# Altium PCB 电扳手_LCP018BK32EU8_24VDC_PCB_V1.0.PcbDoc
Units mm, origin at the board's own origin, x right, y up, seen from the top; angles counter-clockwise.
Board outline 49.67 x 60.1 mm, 2 copper layers (Top Layer, Bottom Layer), stack 1.6 mm thick; 89 components, 55 nets, 390 pads, 196 vias.
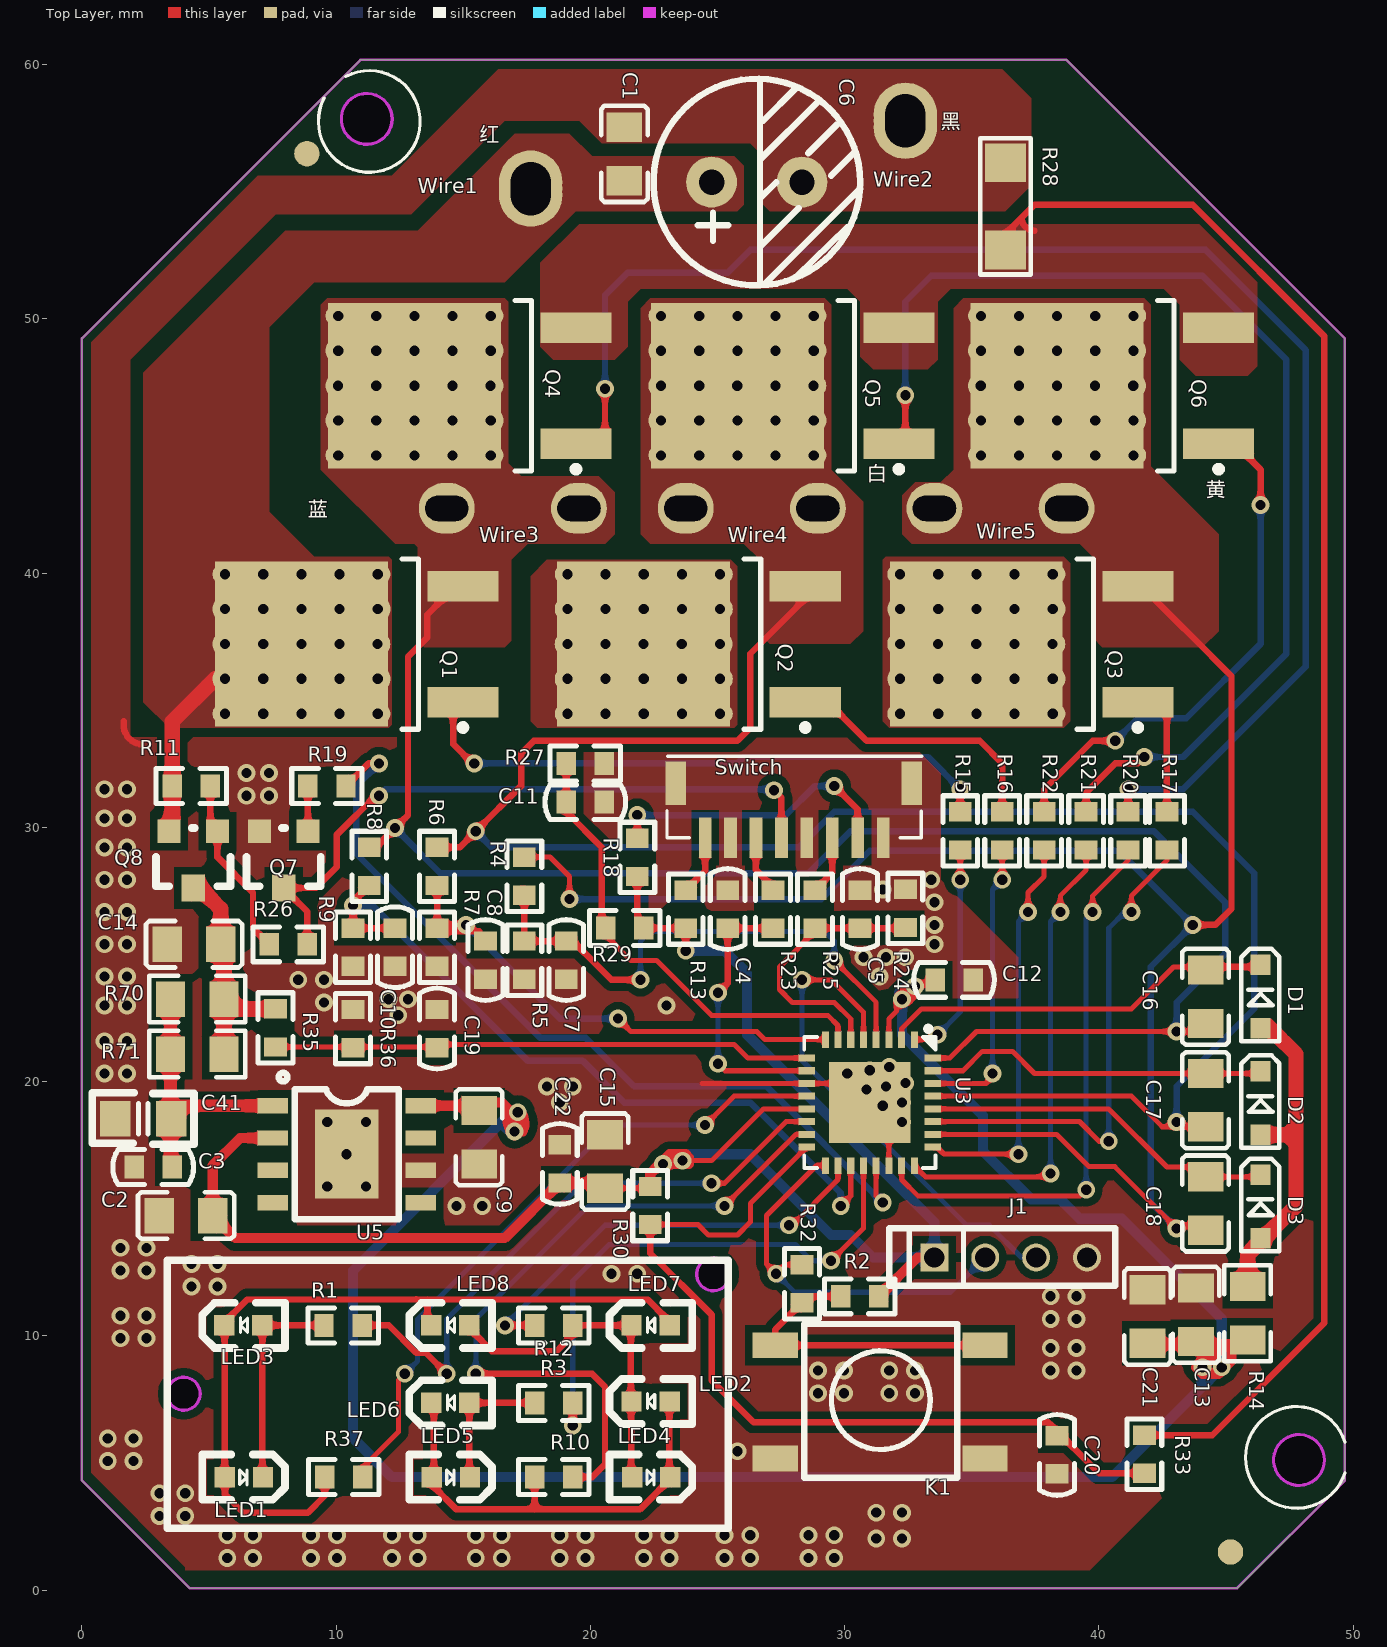
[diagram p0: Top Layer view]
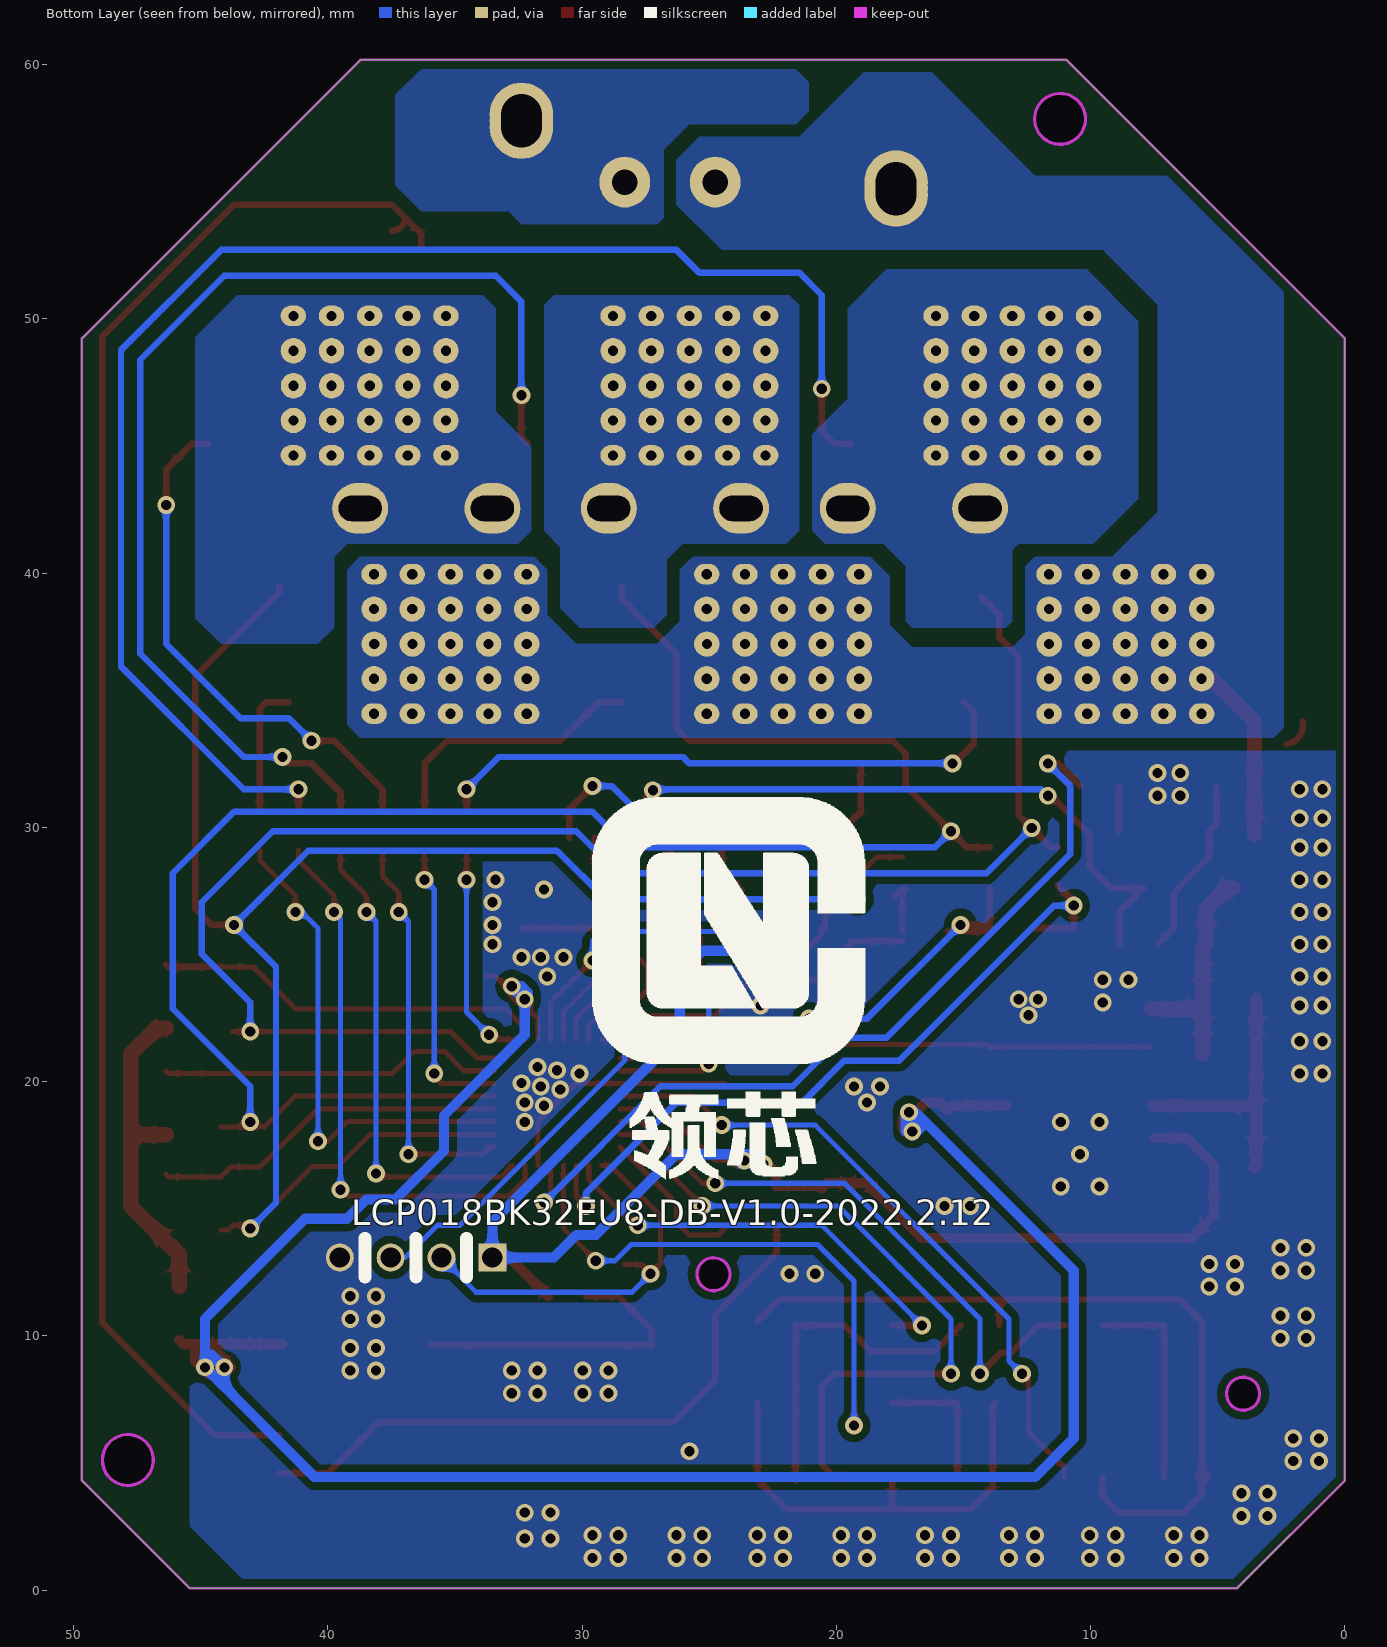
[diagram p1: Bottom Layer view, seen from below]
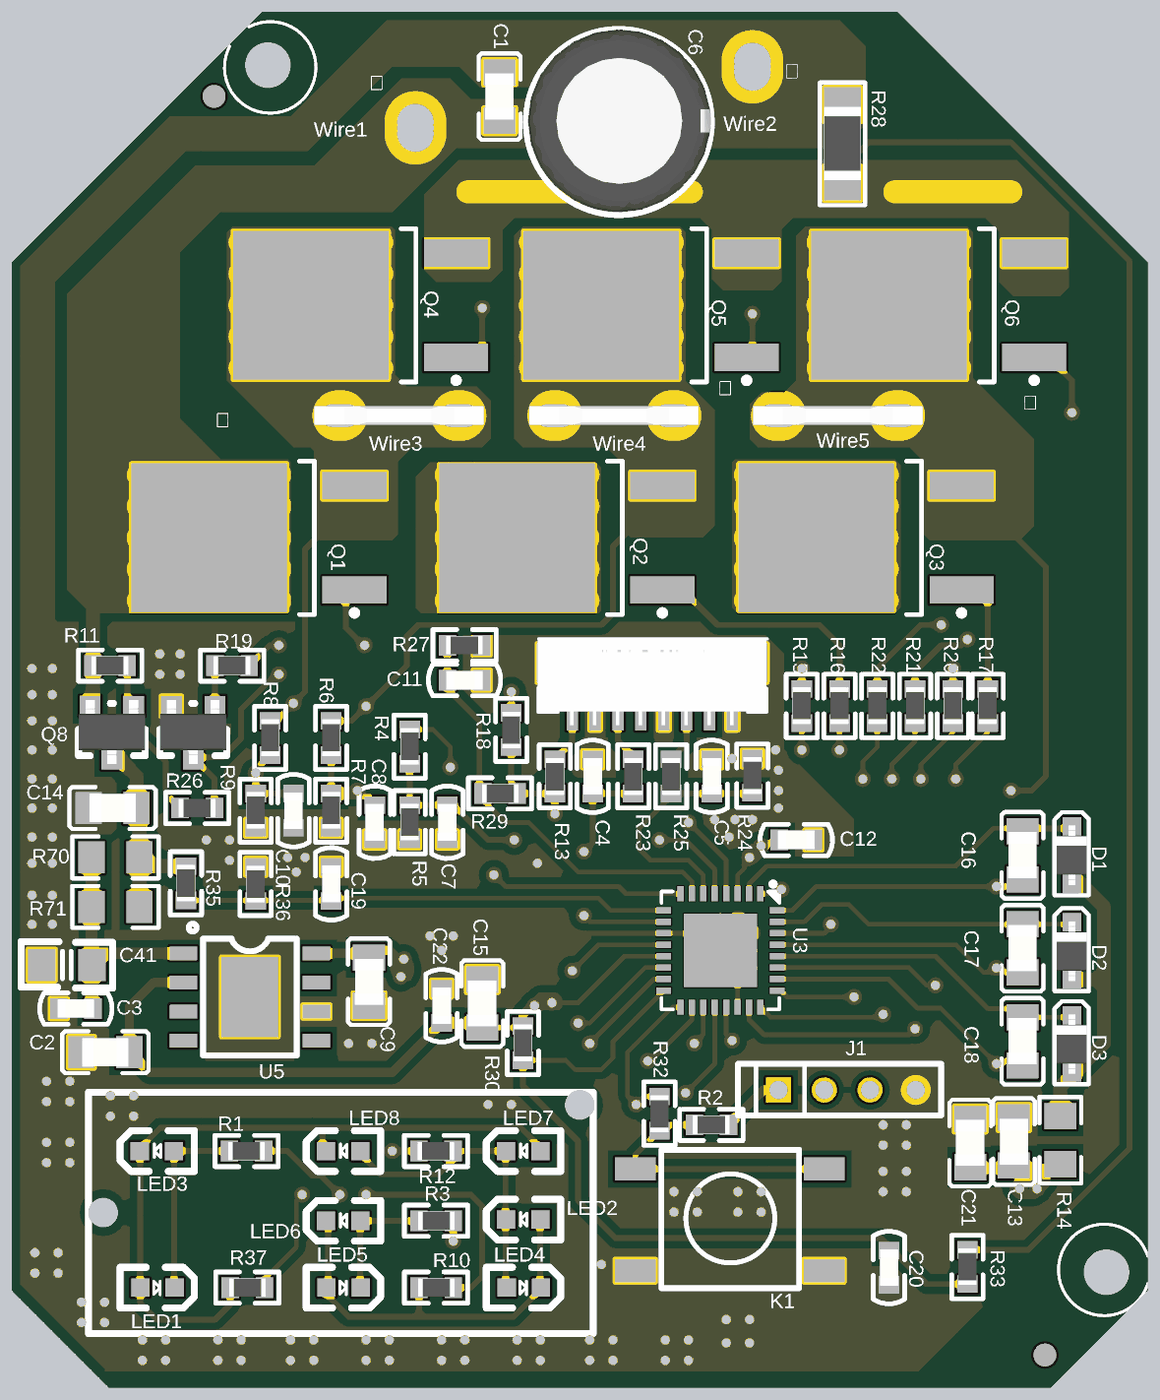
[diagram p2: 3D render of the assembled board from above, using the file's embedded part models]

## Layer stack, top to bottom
Top Solder: solder mask 0.0102, Solder Resist, Dk 3.5
Top Layer: signal copper 0.0356
Dielectric1: core 1.529, FR-4, Dk 4.8
Bottom Layer: signal copper 0.0356
Bottom Solder: solder mask 0.0102, Solder Resist, Dk 3.5

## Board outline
0,4.318 4.239,0.079 45.434,0.079 49.673,4.318 49.673,49.228 38.719,60.182 10.954,60.182 0,49.228
cut-out: 46.865,5.119 ccw(c47.865,5.119) 47.865,4.119 ccw(c47.865,5.119) 48.865,5.119 ccw(c47.865,5.119) 47.865,6.119 ccw(c47.865,5.119)
cut-out: 10.203,57.858 ccw(c11.203,57.858) 11.203,56.858 ccw(c11.203,57.858) 12.203,57.858 ccw(c11.203,57.858) 11.203,58.858 ccw(c11.203,57.858)
cut-out: 3.354,7.724 ccw(c4.004,7.724) 4.004,7.074 ccw(c4.004,7.724) 4.654,7.724 ccw(c4.004,7.724) 4.004,8.374 ccw(c4.004,7.724)
cut-out: 24.182,12.423 ccw(c24.832,12.423) 24.832,11.773 ccw(c24.832,12.423) 25.482,12.423 ccw(c24.832,12.423) 24.832,13.073 ccw(c24.832,12.423)

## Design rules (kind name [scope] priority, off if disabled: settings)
Clearance Clearance_1 [InComponent('U3')] p1: gap=0.125 ignorepadtopadclearanceinfootprint=FALSE except(0: Arc-Hole Track-Hole SMDPad-Hole THPad-Hole Via-Hole Fill-Hole Poly-Hole Region-Hole Text-Hole)
Clearance [All] p2: gap=0.305 ignorepadtopadclearanceinfootprint=FALSE except(0: Arc-Hole Track-Hole SMDPad-Hole THPad-Hole Via-Hole Fill-Hole Poly-Hole Region-Hole Text-Hole)
PolygonConnect [All] p1: connectstyle=Direct reliefconductorwidth=0.254 reliefentries=4 polygonreliefangle="90 Angle" airgapwidth=0.254
RoutingVias [All] p1: holewidth=0.4 width=0.7 viastyle="Through Hole" minholewidth=0.4 minwidth=0.7 maxholewidth=0.711 maxwidth=1.27
SilkToSolderMaskClearance SilkscreenOverComponentPads [IsPad] p1: minsilkscreentomaskgap=0.254 clearancetoexposedcopper=TRUE
SolderMaskExpansion [All] p1: expansion=0.102 istentingtop=FALSE
Width [All] p1: maxlimit=8 minlimit=0.1 preferedwidth=0.254
29 further rules are at their usual default settings.

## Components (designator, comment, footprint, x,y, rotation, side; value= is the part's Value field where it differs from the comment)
C1 "10uF/25V" 0805C#1 21.336,57.531 r270 top
C2 "10uF/10V" 0805C#1 3.048,14.732 r0 top
C3 "104/50V" 0603C#1 3.556,16.637 r180 top
C4 "103/50V" 0603C#1 25.4,26.035 r90 top
C5 "103/50V" 0603C#1 30.607,26.035 r90 top
C6 "330uF/25V" RB8*12 24.765,55.372 r180 top
C7 "101/50V" 0603C#1 19.05,25.527 r270 top
C8 "101/50V" 0603C#1 15.875,25.527 r270 top
C9 "10uF/25V" 0805C#1 15.621,16.764 r90 top
C10 "101/50V" 0603C#2 12.319,26.035 r270 top
C11 "103/50V" 0603C#1 19.05,30.988 r0 top
C12 "104/50V" 0603C#1 35.052,24.003 r180 top
C13 "10uF/25V" 0805C#1 43.815,9.779 r90 top
C14 "10uF/25V" 0805C#2 5.461,25.4 r180 top
C15 "10uF/10V" 0805C#1 20.574,17.907 r270 top
C16 "2.2uF/25V" 0805C#1 44.196,24.384 r270 top
C17 "2.2uF/25V" 0805C#1 44.196,20.32 r270 top
C18 "2.2uF/25V" 0805C#1 44.196,16.256 r270 top
C19 "103/50V" 0603C#1 13.97,21.336 r90 top
C20 "101/50V" 0603C#2 38.354,4.572 r90 top
C21 "10uF/25V" 0805C#1 41.91,11.811 r270 top
C22 "104/50V" 0603C#1 18.796,16.014 r90 top
C41 "10uF/25V" C0805 2.413,18.542 r0 top
D1 "SD103AW" SOD323 46.355,22.098 r90 top
D2 "SD103AW" SOD323 46.355,17.907 r90 top
D3 "SD103AW" SOD323 46.355,13.843 r90 top
J1 "CON4" SIP4-2.0C 33.528,13.081 r0 top
K1 "K6*6*5" SP-SMT6*6*5 27.265,9.629 r0 top
LED1 "R1(G)" 0603LED(G) 5.626,4.445 r180 top
LED2 "R2(G)" 0603LED(G) 23.114,7.419 r0 top
LED3 "R3(G)" 0603LED(G) 7.099,10.414 r0 top
LED4 "G1(G)" 0603LED(G) 21.641,4.445 r180 top
LED5 "G2(G)" 0603LED(G) 13.767,4.445 r180 top
LED6 "G3(G)" 0603LED(G) 15.24,7.366 r0 top
LED7 "R1(G)" 0603LED(G) 23.114,10.414 r0 top
LED8 "R1(G)" 0603LED(G) 15.24,10.414 r0 top
Q1 "MDD1501" D-PAK1 14.986,34.925 r90 top
Q2 "MDD1501" D-PAK1 28.448,34.925 r90 top
Q3 "MDD1501" D-PAK1 41.529,34.925 r90 top
Q4 "MDD1501" D-PAK1 19.431,45.085 r90 top
Q5 "MDD1501" D-PAK1 32.131,45.085 r90 top
Q6 "MDD1501" D-PAK1 44.704,45.085 r90 top
Q7 "S9014" SOT-23 8.89,29.845 r180 top
Q8 "MMBT5401" SOT-23 5.334,29.845 r180 top
R1 "510R" 0603R#1 9.525,10.414 r0 top
R2 "10K" 0603R#1 29.845,11.557 r0 top
R3 "510R" 0603R#1 19.304,7.366 r180 top
R4 "20K 1%" 0603R#1 17.399,28.829 r270 top
R5 "2.4K 1%" 0603R#1 17.399,25.527 r270 top
R6 "20K 1%" 0603R#1 13.97,29.21 r270 top
R7 "2.4K 1%" 0603R#1 13.97,26.035 r270 top
R8 "20K 1%" 0603R#1 11.303,29.21 r270 top
R9 "2.4K 1%" 0603R#1 10.668,26.035 r270 top
R10 "510R" 0603R#1 19.304,4.445 r180 top
R11 "100K" 0603R#1 3.556,31.623 r0 top
R12 "510R" 0603R#1 17.805,10.414 r0 top
R13 "100R" 0603R#1 23.749,26.035 r90 top
R14 "5.1R 5% 0805" 0805R 45.847,11.938 r270 top
R15 "51R" 0603R#1 34.544,30.607 r270 top
R16 "51R" 0603R#1 36.195,30.607 r270 top
R17 "51R" 0603R#1 42.672,30.607 r270 top
R18 "100R" 0603R#1 21.844,28.067 r90 top
R19 "1K" 0603R#1 8.89,31.623 r0 top
R20 "51R" 0603R#1 41.148,30.607 r270 top
R21 "51R" 0603R#1 39.497,30.607 r270 top
R22 "51R" 0603R#1 37.846,30.607 r270 top
R23 "1K" 0603R#1 27.178,26.035 r90 top
R24 "220K 1%" 0603R#1 32.385,27.559 r270 top
R25 "1K" 0603R#2 28.829,26.035 r90 top
R26 "5.1K" 0603R#1 7.366,25.4 r0 top
R27 "100K NTC B=4250" 0603R#1 19.05,32.512 r0 top
R28 "0.001R/1W" 1206A 36.322,52.705 r90 top
R29 "10K 1%" 0603R#1 22.098,26.035 r180 top
R30 "220K 1%" 0603R#1 22.352,15.875 r270 top
R32 "1K" 0603R#1 28.321,11.303 r90 top
R33 "6.8K 1%" 0603R#1 41.783,6.096 r270 top
R35 "10K 1%" 0603R#1 7.62,22.86 r270 top
R36 "1K 1%" 0603R#1 10.668,21.336 r90 top
R37 "510R" 0603R#1 11.049,4.445 r180 top
R70 "10R 5%" 0805R 5.588,23.241 r180 top
R71 "10R 5%" 0805R 5.588,21.082 r180 top
Switch "SHL-8P" SHL1.0-8 24.511,29.591 r180 top
U3 "LCP018B32B" QFN-32 30.988,19.177 r270 top
U5 "EG1205" ESOP-8 10.414,17.145 r270 top
Wire1 "Wire#18-(Red)cm" WIRE#18-RED7CM 17.653,55.118 r90 top
Wire2 "Wire#18-(BK)cm" WIRE#18-BK7CM 32.385,57.785 r90 top
Wire3 "W-(BL)" LEAF1 14.351,42.545 r0 top
Wire4 "W-(WT)" LEAF1 23.749,42.545 r0 top
Wire5 "W-(YE)" LEAF1 33.528,42.545 r0 top

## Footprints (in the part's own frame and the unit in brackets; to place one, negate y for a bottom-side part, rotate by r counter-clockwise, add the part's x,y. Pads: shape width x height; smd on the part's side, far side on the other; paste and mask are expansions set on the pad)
0603C#1 [mm]
  rect 0.762x0.9 smd: 1(0,0) 2(1.497,0)
  silkscreen extent -0.84,-0.69 2.34,0.69, body extent -0.05,-0.41 1.55,0.4, height 0.89
0603C#2 [mm]
  rect 0.762x0.9 smd mask+0: 1(0,0) 2(1.497,0)
  silkscreen extent -0.84,-0.69 2.34,0.69, body extent -0.05,-0.41 1.55,0.4, height 0.89
0603LED(G) [mm]
  rect 0.8x0.8 smd: 1(0,0) 2(-1.5,0)
  silkscreen extent -2.36,-0.89 0.89,0.89, body extent -1.5,-0.43 0,0.46, height 1.2
0603R#1 [mm]
  rect 0.762x0.9 smd: 1(0,0) 2(1.497,0)
  silkscreen extent -0.64,-0.69 2.13,0.69, body extent -0.06,-0.4 1.54,0.4, height 0.46
0603R#2 [mm]
  rect 0.762x0.9 smd mask+0: 1(0,0) 2(1.497,0)
  silkscreen extent -0.64,-0.69 2.13,0.69, body extent -0.06,-0.4 1.54,0.4, height 0.46
0805C#1 [mm]
  rect 1.15x1.4 smd: 1(0,0) 2(2.1,0)
  silkscreen extent -0.84,-0.91 2.94,0.91, body extent 0.04,-0.63 2.05,0.62, height 0.93
0805C#2 [mm]
  rect 1.15x1.4 smd: 1(0,0)
  rect 1.15x1.4 smd mask+0: 2(2.1,0)
  silkscreen extent -0.84,-0.91 2.94,0.91, body extent 0.04,-0.63 2.05,0.62, height 0.93
0805R [mm]
  rect 1.15x1.4 smd: 1(0,0) 2(2.1,0)
  silkscreen extent -0.84,-0.91 2.94,0.91
1206A [mil]
  rect 60x62.99 smd: 1(0,0) 2(135,0)
  silkscreen extent -38,-39 173,39, body extent 5,-31 131,31, height 24
C0805 [mm]
  rect 1.2x1.4 smd: 1(-1.1,0) 2(1.1,0)
  silkscreen extent -2,-1.01 2,1.02
D-PAK1 [mm]
  rect 1.2x2.8 smd: 1(0,0) 3(4.56,0)
  oval 0.813x1 hole 0.4: 2(-0.457,9.35) 2(-0.457,7.85) 2(-0.457,6.35) 2(-0.457,4.85) 2(-0.457,3.35) 2(5.029,6.35) 2(5.029,7.85) 2(5.029,9.35) 2(5.029,3.35) 2(5.029,4.85)
  round 1 hole 0.4: 2(0.914,7.85) 2(0.914,9.35) 2(0.914,4.85) 2(0.914,6.35) 2(0.914,3.35) 2(2.28,9.354) 2(2.28,3.354) 2(2.28,4.854) 2(2.28,6.354) 2(2.28,7.854) 2(3.658,6.35) 2(3.658,7.85) 2(3.658,9.35) 2(3.658,3.35) 2(3.658,4.85)
  rect 6.5x6.8 smd: 2(2.28,6.354)
  silkscreen extent -1.12,-0.13 5.63,2.4
ESOP-8 [mm] "EG1205"
  rect 0.6x1.2 smd: 1(-1.905,-2.908) 2(-0.635,-2.908) 3(0.635,-2.908) 4(1.905,-2.908) 5(1.905,2.908) 6(0.635,2.908) 7(-0.635,2.908) 8(-1.905,2.908)
  rect 3.5x2.5 smd: 9(0,0)
  silkscreen extent -3.2,-2.67 2.55,2.05
LEAF1 [mm]
  oval 2.2x2 hole 1 slot 1.7 at 0 deg: 0(0,0) 0(5.2,0)
  body extent -1.11,-0.39 6.29,0.41, height 8.5
QFN-32 [mm]
  rect 0.65x0.28 smd mask+0.051: 1(-2.478,1.75) 2(-2.478,1.25) 3(-2.478,0.75) 4(-2.478,0.25) 5(-2.478,-0.25) 6(-2.478,-0.75) 7(-2.478,-1.25) 8(-2.478,-1.75) 17(2.478,-1.75) 18(2.478,-1.25) 19(2.478,-0.75) 20(2.478,-0.25) 21(2.478,0.25) 22(2.478,0.75) 23(2.478,1.25) 24(2.478,1.75)
  rect 0.28x0.65 smd mask+0.051: 9(-1.75,-2.478) 10(-1.25,-2.478) 11(-0.75,-2.478) 12(-0.25,-2.478) 13(0.25,-2.478) 14(0.75,-2.478) 15(1.25,-2.478) 16(1.75,-2.478) 25(1.75,2.478) 26(1.25,2.478) 27(0.75,2.478) 28(0.25,2.478) 29(-0.25,2.478) 30(-0.75,2.478) 31(-1.25,2.478) 32(-1.75,2.478)
  rect 3.2x3.2 smd mask+0.051: 22(0,0)
  silkscreen extent -3,-2.58 2.58,2.58
RB8*12 [mm]
  round 2 hole 1: 1(0,0) 2(-3.556,0)
  silkscreen extent -5.84,-4.06 2.28,4.06, body extent -5.81,-4.05 2.2,3.95, height 12.5
SHL1.0-8 [mm]
  rect 0.5x1.6 smd: 1(0,0) 2(-1,0) 3(-2,0) 4(-3,0) 5(-4,0) 6(-5,0) 7(-6,0) 8(-7,0)
  rect 0.8x1.7 smd: 9(1.151,-2.145) 10(-8.126,-2.145)
  silkscreen extent -8.52,-3.2 1.5,0, body extent -8.48,-3.23 1.52,0.57, height 4.5
SIP4-2.0C [mm]
  rect 1.1x1.1 hole 0.8: 1(0,0)
  round 1.1 hole 0.8: 2(2,0) 3(4,0) 4(6,0)
  silkscreen extent -1.77,-1.12 7.11,1.14
SOD323 [mm]
  rect 0.8x0.8 smd: 1(0,0) 2(2.5,0)
  silkscreen extent -0.51,-0.74 3.12,0.76, body extent -0.06,-0.64 2.54,0.66, height 1
SOT-23 [mil]
  rect 36x36 smd: 1(0,0) 2(75,0)
  rect 36x42.13 smd: 3(37.5,87.87)
  silkscreen extent -20,-5 95,85, body extent -20,-11 94,99, height 47
SP-SMT6*6*5 [mil]
  rect 70x40 smd: 1(0,0) 1(325,0) 2(0,-175) 2(325,-175)
  silkscreen extent 45,-205 282,33, body extent 45,-205 280,30, height 197
WIRE#18-BK7CM [mm]
  round 2.5 hole 1.6: 0(-0.25,0) 0(0,0) 0(0.25,0)
  body extent -1.04,-1.05 1.05,1.05, height 66.4
WIRE#18-RED7CM [mm]
  round 2.5 hole 1.6: 0(-0.25,0) 0(0,0) 0(0.25,0)
  body extent -1.04,-1.05 1.05,1.05, height 66.4

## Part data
C1: library part Cap, "Capacitor"
C2 C4 C7 C8 C9 C10 C20 C21: library part CAP
C3 C5 C12 C13 C14 C15 C22 C41: library part CAP, "Capacitor"
C6: library part ELECTRO1, "Electrolytic Capacitor"
C11 C17 C18 C19: library part "Cap Semi", "Capacitor (Semiconductor SIM Model)"
C16: library part "Cap Semi", "Capacitor (Semiconductor S"
D1 D2 D3: library part DIODE, "SBD"
K1: library part K
LED1 LED2 LED3 LED4 LED5 LED6 LED7 LED8: library part LED1
Q1 Q2 Q3 Q4 Q5 Q6: library part RJK
Q7: library part NPN1
Q8: library part PNP1
R1 R2 R3 R4 R5 R6 R7 R8 R9 R10 R12 R13 R18 R19 R24 R30 R32 R33 R37: library part RES2
R11 R15 R16 R17 R20 R21 R22 R26 R28 R29 R35 R36: library part Res2, "Resistor"
R14 R70 R71: library part RES
R23 R25: library part RES2, "Resistor"
R27: library part VARISTOR, "TemR"
Switch: library part 8PIN
Wire1 Wire2 Wire3 Wire4 Wire5: library part Wire

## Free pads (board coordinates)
  round 1 smd: 0(8.85,56.492) 0(45.172,1.501)

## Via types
v1: diameter 0.7, hole 0.4, Top Layer to Bottom Layer, tented both sides, 196 vias

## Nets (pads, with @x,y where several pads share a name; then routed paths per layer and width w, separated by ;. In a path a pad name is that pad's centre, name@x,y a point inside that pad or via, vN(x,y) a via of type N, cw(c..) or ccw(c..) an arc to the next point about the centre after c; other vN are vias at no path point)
+12V: C9.2 C12.2 C13.1 C21.2 R14.2 U3.3 U5.8 | length 103.9
  Top Layer w0.2: U3.3 31.738,22.467 32.03,22.759 32.03,23.394 32.385,23.749 v1(32.766,23.749) 33.02,23.749 33.428,24.157 C12.2@33.782,24.157
  Top Layer w0.254: 16.764,18.923 ccw(c17.415,18.526) v1@17.018,17.875 ; v1@16.912,18.14 cw(c17.426,18.432) 17.134,18.946 cw(c16.811,18.357) v1@17.351,17.959 ; v1@17.148,18.109 ccw(c16.909,18.451) v1@17.251,18.69 ; 32.037,22.932 ccw(c31.909,23.924) v1@32.893,23.749 ; v1(32.258,23.241) ccw(c32.271,23.716) v1@32.747,23.703 ; v1@43.815,8.763 cw(c44.543,8.636) 44.67,9.364
  Top Layer w0.4: U5.8 15.435,19.05 C9.2 15.934,19.177 16.51,19.177 16.764,18.923 16.931,18.756 17.018,18.669 17.018,18.14 17.018,18.109 v1@17.018,17.875 ; C21.2@41.783,9.668 C13.1@43.815,9.668 ; v1@43.815,8.763 44.069,8.509 44.704,8.509 45.212,9.017 R14.2@45.212,9.398 ; C13.1 C13.1@43.815,9.668 ; v1(44.069,8.763) 44.974,9.668 ; R14.2 45.677,9.668 44.974,9.668 ; C13.1@43.815,9.668 44.974,9.668
  Bottom Layer w0.254: 16.455,18.36 ccw(c17.027,18.605) 17.272,18.034 cw(c17.209,18.605) 16.637,18.542 ; v1@16.891,18.796 ccw(c17.416,18.652) v1@17.272,18.127
  Bottom Layer w0.4: v1@17.272,18.034 17.272,18.669 v1(17.145,18.796) 16.891,18.796 10.668,12.573 10.668,5.969 12.192,4.445 40.513,4.445 v1(44.831,8.763) 44.831,10.668 40.894,14.605 39.243,14.605 38.481,15.367 37.338,15.367 35.433,17.272 35.433,18.669 32.258,21.844 v1(32.258,23.241) v1(32.766,23.749) 32.385,23.749 32.131,23.495 v1@32.131,23.241 ; 44.069,8.001 v1(44.069,8.763) 44.577,9.271
  other v1: 17.018,18.034
DCIN: C1.2 C6.1 Q1.2 Q2.2 Q3.2 Q8.2 R11.1 Wire1.0 | length 7.2
  Top Layer w0.6: Q8.2@3.556,29.718 3.556,31.369 3.556,34.163 5.232,35.839 Q1.2@5.636,35.839
FOR: C4.1 R23.1 U3.10 | length 11
  Top Layer w0.2: v1(25.019,20.701) 25.293,20.427 U3.10
  Top Layer w0.254: v1(25.019,23.495) 25.4,23.876 C4.1 R23.1@27.305,26.035
  Bottom Layer w0.2: v1(25.019,20.701) v1(25.019,23.495)
GAH: Q1.1 R15.1 | length 23.7
  Top Layer w0.254: Q1.1 14.605,34.544 14.605,33.274 15.367,32.512 v1(15.43,32.512) ; R15.1 v1(34.544,31.496)
  Bottom Layer w0.254: v1(15.43,32.512) 25.781,32.512 26.035,32.766 33.274,32.766 v1(34.544,31.496) ; v1@34.48,31.432 v1@34.544,31.369
GAL: Q4.1 R20.1 | length 58.8
  Top Layer w0.254: Q4.1 20.066,45.085 20.574,45.593 v1(20.574,47.244) ; R20.1 v1(41.148,31.496)
  Bottom Layer w0.254: v1@20.574,47.371 20.574,50.927 21.463,51.816 25.4,51.816 26.289,52.705 44.196,52.705 48.133,48.768 48.133,36.322 43.307,31.496 v1(41.148,31.496)
GBH: Q2.1 R16.1 | length 10.7
  Top Layer w0.254: Q2.1 29.337,34.925 30.861,33.401 35.306,33.401 36.195,32.512 R16.1
GBL: Q5.1 R21.1 | length 44.9
  Top Layer w0.254: Q5.1 32.385,45.339 v1(32.385,46.99) ; R21.1 39.497,31.369 40.64,32.512 41.529,32.512 v1(41.783,32.766)
  Bottom Layer w0.254: v1(32.385,46.99) 32.385,50.673 33.401,51.689 44.069,51.689 47.371,48.387 47.371,36.83 43.307,32.766 v1(41.783,32.766)
GCH: Q3.1 R17.1 | length 5.3
  Top Layer w0.254: Q3.1 42.418,34.925 42.672,34.671 R17.1
GCL: Q6.1 R22.1 | length 20.7
  Top Layer w0.254: R22.1 37.846,31.496 39.751,33.401 v1(40.64,33.401) ; Q6.1 45.339,45.085 46.355,44.069 v1(46.355,42.672)
  Bottom Layer w0.254: v1(40.64,33.401) 41.529,34.29 43.434,34.29 46.355,37.211 v1(46.355,42.672)
GND: C1.1 C2.1 C3.2 C4.2 C5.2 C6.2 C7.2 C8.2 C9.1 C10.2 C11.2 C12.1 C13.2 C14.2 C15.1 C19.2 C20.1 C21.1 C22.2 C41.1 J1.4 K1.2 Q7.2 R5.2 R7.2 R9.2 R24.1 R27.2 R28.2 R36.2 Switch.2 Switch.5 Switch.8 Switch.9 Switch.10 U3.11 U3.22 U5.6 U5.9 Wire2.0 | length 10.9
  Top Layer w0.2: 24.396,19.927 U3.11 30.238,19.927 30.988,19.177 31.738,18.427 U3.22@31.738,16.699
  Top Layer w0.254: 1.651,34.163 ccw(c2.413,34.036) 2.286,33.274
  other v1: 5.715,1.27 6.731,1.27 9.017,1.27 10.033,1.27 12.192,1.27 13.208,1.27 15.494,1.27 16.51,1.27 18.796,1.27 19.812,1.27 22.098,1.27 23.114,1.27 25.273,1.27 26.289,1.27 28.575,1.27 29.591,1.27 31.242,2.032 32.258,2.032 5.715,2.159 6.731,2.159 9.017,2.159 10.033,2.159 12.192,2.159 13.208,2.159 15.494,2.159 16.51,2.159 18.796,2.159 19.812,2.159 22.098,2.159 23.114,2.159 25.273,2.159 26.289,2.159 28.575,2.159 29.591,2.159 3.048,2.921 4.064,2.921 31.242,3.048 32.258,3.048 3.048,3.81 4.064,3.81 1.016,5.08 2.032,5.08 25.781,5.461 1.016,5.969 2.032,5.969 28.956,7.747 29.972,7.747 31.75,7.747 32.766,7.747 28.956,8.636 29.972,8.636 31.75,8.636 32.766,8.636 38.1,8.636 39.116,8.636 38.1,9.525 39.116,9.525 1.524,9.906 2.54,9.906 38.1,10.668 39.116,10.668 1.524,10.795 2.54,10.795 38.1,11.557 39.116,11.557 4.318,11.938 5.334,11.938 20.828,12.446 21.844,12.446 1.524,12.573 2.54,12.573 4.318,12.827 5.334,12.827 1.524,13.462 2.54,13.462 14.732,15.113 15.748,15.113 9.652,15.875 11.176,15.875 10.414,17.145 9.652,18.415 11.176,18.415 32.258,18.415 31.496,19.05 18.796,19.177 32.258,19.177 30.861,19.685 18.288,19.812 19.304,19.812 31.623,19.812 32.385,19.939 0.889,20.32 1.778,20.32 30.099,20.32 30.988,20.447 31.75,20.574 0.889,21.59 1.778,21.59 12.446,22.606 0.889,22.987 1.778,22.987 22.987,22.987 9.525,23.114 12.065,23.241 12.827,23.241 8.509,24.003 9.525,24.003 0.889,24.13 1.778,24.13 31.369,24.13 30.734,24.892 31.623,24.892 32.385,24.892 0.889,25.4 1.778,25.4 33.528,25.4 33.528,26.162 0.889,26.67 1.778,26.67 33.528,27.051 31.496,27.559 0.889,27.94 1.778,27.94 33.401,27.94 0.889,29.21 1.778,29.21 0.889,30.353 1.778,30.353 6.477,31.242 7.366,31.242 0.889,31.496 1.778,31.496 6.477,32.131 7.366,32.131
IBUS: C20.2 R30.2 R33.2 U3.16 | length 34
  Top Layer w0.2: R30.2 24.23,14.378 24.638,13.97 25.781,13.97 26.289,14.478 26.289,15.206 U3.16
  Top Layer w0.254: R30.2 22.352,13.251 24.765,10.838 24.765,8.255 26.416,6.604 38,6.604 40.005,4.599 R33.2@41.91,4.599
IN: C14.1 Q8.3 R35.1 R70.1 R71.1 | length 9.2
  Top Layer w0.6: Q8.3 4.645,27.613 5.461,26.797 C14.1 5.588,25.273 R70.1 R70.1@5.588,22.86 ; R71.1 R70.1@5.588,22.86 ; R35.1 R70.1@5.588,22.86
ISENCE: Q4.3 Q5.3 Q6.3 R28.1 R33.1 | length 64.2
  Top Layer w0.254: R28.1 36.322,53.34 36.957,53.975 ; 37.465,53.467 cw(c37.465,53.975) 36.957,53.975 ; R33.1@41.91,6.096 42.465,6.096 44.45,6.096 48.865,10.511 48.865,49.306 43.688,54.483 37.465,54.483 36.957,53.975
LED1: R1.2 U3.14 | length 23.7
  Top Layer w0.2: v1(24.765,16.002) 25.273,16.002 27.698,18.427 U3.14
  Top Layer w0.254: R1.2 12.065,10.414 13.144,9.335 13.525,9.335 v1(14.351,8.509)
  Bottom Layer w0.2: v1(14.351,8.509) 14.351,10.668 19.685,16.002 v1(24.765,16.002)
LED2: R37.1 U3.12 | length 26.2
  Top Layer w0.2: R37.1 11.049,4.826 12.446,6.223 12.446,8.255 v1(12.7,8.509) ; v1(24.511,18.288) 25.65,19.427 U3.12
  Bottom Layer w0.2: v1@12.573,8.509 v1(12.7,8.509) 13.208,9.017 13.208,10.668 20.828,18.288 v1(24.511,18.288)
LED3: R12.1 U3.18 | length 17.2
  Top Layer w0.2: v1@27.877,14.287 29.738,16.149 U3.18
  Top Layer w0.254: v1(16.637,10.414) R12.1
  Bottom Layer w0.2: v1(16.637,10.414) 20.574,14.351 v1(27.813,14.351)
LED4: R10.1 U3.15 | length 28
  Top Layer w0.2: v1(25.273,15.113) 28.087,17.927 U3.15
  Top Layer w0.254: v1(15.494,8.509) 20.066,8.509 20.574,8.001 20.574,4.953 20.066,4.445 R10.1
  Bottom Layer w0.2: v1(15.494,8.509) 15.494,10.668 19.939,15.113 v1(25.273,15.113)
LED5: R3.1 U3.20 | length 21.9
  Top Layer w0.2: v1(29.464,12.954) 30.738,14.228 U3.20
  Top Layer w0.254: v1(19.304,6.477) R3.1
  Bottom Layer w0.2: v1(19.304,6.477) 19.304,12.155 20.738,13.589 28.067,13.589 28.702,12.954 v1(29.464,12.954)
MOSTEMP: C11.1 R27.1 R29.2 U3.7 | length 18.5
  Top Layer w0.2: R29.2 20.601,25.754 21.59,24.765 22.606,24.765 24.765,22.606 29.337,22.606 29.738,22.205 U3.7
  Top Layer w0.254: R27.1 19.05,30.607 20.447,29.21 R29.2@20.447,26.035
MOTOR_A: C16.2 Q1.3 Q4.2 R8.1 U3.32 Wire3.0 | length 63
  Top Layer w0.2: U3.32 34.135,20.927 35.179,21.971 v1(43.053,21.971) C16.2@43.756,21.971
  Top Layer w0.254: R8.1 11.557,29.21 12.827,30.48 12.827,36.703 13.589,37.465 13.589,38.354 Q1.3@14.287,39.052
  Bottom Layer w0.254: v1(12.319,29.972) 14.097,28.194 28.575,28.194 30.226,29.845 42.164,29.845 44.958,27.051 44.958,25.019 43.053,23.114 v1(43.053,21.971)
MOTOR_B: C17.2 Q2.3 Q5.2 R6.1 U3.29 Wire4.0 | length 76.2
  Top Layer w0.2: U3.29 41.279,19.427 42.486,18.22 C17.2
  Top Layer w0.254: R6.1 14.859,29.21 v1(15.494,29.845) 17.272,31.623 17.272,32.893 17.78,33.401 25.781,33.401 26.289,33.909 26.289,36.83 28.448,38.989 Q2.3
  Bottom Layer w0.254: v1(15.494,29.845) 16.129,29.21 28.194,29.21 29.591,30.607 43.688,30.607 46.101,28.194 46.101,22.86 43.053,19.812 v1(43.053,18.415)
MOTOR_C: C18.2 Q3.3 Q6.2 R4.1 U3.26 Wire5.0 | length 70.7
  Top Layer w0.2: R4.1 18.415,28.829 19.177,28.067 v1(19.177,27.178) ; U3.26 38.334,17.927 39.605,16.656 40.621,16.656 42.926,14.351 43.726,14.351 43.921,14.156 C18.2
  Top Layer w0.254: Q3.3@41.91,39.497 41.91,39.243 42.303,38.85 42.737,38.416 43.17,37.983 43.604,37.549 45.212,35.941 45.212,26.797 44.577,26.162 44.226,26.162 v1(43.688,26.162)
  Bottom Layer w0.254: v1(19.177,27.178) 29.083,27.178 30.988,29.083 40.767,29.083 v1(43.688,26.162) 42.037,24.511 42.037,15.24 v1(43.053,14.224)
NetC3_1: C3.1 C41.2 R70.2 R71.2 U5.1 | length 10.6
  Top Layer w0.5: R70.2 R71.2 C41.2@3.488,19.05 ; C3.1 3.488,16.705 C41.2@3.488,19.05 ; U5.1 C41.2@3.488,19.05
NetC16_1: C16.1 D1.2 U3.2 | length 15.6
  Top Layer w0.2: U3.2 32.238,22.078 33.02,22.86 41.275,22.86 42.926,24.511 C16.1@44.196,24.511
  Top Layer w0.254: C16.1@44.196,24.511 46.268,24.511 D1.2
NetC17_1: C17.1 D2.2 U3.31 | length 13.6
  Top Layer w0.2: U3.31 34.651,20.427 35.413,21.189 36.596,21.189 37.465,20.32 C17.1 46.268,20.32 D2.2
NetC18_1: C18.1 D3.2 U3.28 | length 14
  Top Layer w0.2: U3.28 40.382,18.927 42.672,16.637 43.815,16.637 C18.1 46.268,16.256 D3.2
NetD1_1: D1.1 D2.1 D3.1 R14.1 | length 14.8
  Top Layer w0.254: 47.117,17.78 cw(c47.053,17.208) 47.625,17.145 ; 47.117,18.034 ccw(c47.053,18.606) 47.625,18.669
  Top Layer w0.6: R14.1 45.847,13.208 47.752,15.113 47.752,21.082 46.736,22.098 D1.1 ; D2.1 47.625,17.907
NetK1_1: K1.1 R2.1 R32.1 | length 12.4
  Top Layer w0.254: R2.1 28.575,11.557 R32.1 27.265,10.247 27.265,9.629 35.52,9.629 K1.1@35.964,9.629
NetLED1_1: LED1.1 LED3.2 LED7.1 LED8.2 R37.2 | length 31.9
  Top Layer w0.254: LED1.1@5.612,4.469 5.612,10.541 6.501,11.43 13.589,11.43 ; LED1.1 5.626,3.772 6.35,3.048 8.89,3.048 9.552,3.71 R37.2 ; 13.081,11.43 cw(c13.144,10.986) 13.589,11.049 ; LED8.2@13.589,10.438 13.589,11.43 ; LED7.1@23.114,10.57 22.254,11.43 13.589,11.43
  Top Layer w0.6: LED1.1@5.588,4.445 LED1.1@5.612,4.469
NetLED1_2: LED1.2 LED3.1 R1.1 | length 8.4
  Top Layer w0.254: LED1.2 7.099,4.472 LED3.1 R1.1
NetLED2_1: LED2.1 LED4.2 LED5.1 LED6.2 R10.2 | length 18.8
  Top Layer w0.254: LED6.2 13.843,7.263 13.843,4.064 14.732,3.175 17.807,3.175 ; 17.526,3.175 ccw(c17.54,3.443) 17.807,3.429 ; 17.807,3.556 ccw(c18.175,3.542) 18.161,3.175 ; R10.2 17.807,3.175 ; LED4.2@23.09,4.318 21.947,3.175 17.807,3.175 ; LED4.2@23.102,4.318 LED2.1@23.102,7.419
NetLED2_2: LED2.2 LED4.1 LED7.2 LED8.1 R12.2 | length 13.5
  Top Layer w0.254: LED8.1@15.113,10.414 16.129,9.398 18.669,9.398 19.685,10.414 LED7.2 ; LED4.1@21.59,4.318 21.602,4.33 LED2.2@21.602,7.419 ; LED2.2@21.59,7.419 LED7.2@21.59,10.438
NetLED5_2: LED5.2 LED6.1 R3.2 | length 5.4
  Top Layer w0.254: LED5.2@15.24,4.548 LED6.1 R3.2
NetQ7_1: Q7.1 R19.1 | length 1.8
  Top Layer w0.254: Q7.1 R19.1
NetQ8_1: Q8.1 R11.2 R26.1 | length 7.2
  Top Layer w0.254: R11.2 5.053,30.126 Q8.1 5.334,28.829 6.731,27.432 6.731,26.035 R26.1
NetR13_2: R13.2 Switch.1 | length 2.4
  Top Layer w0.254: R13.2 24.511,28.294 Switch.1
NetR15_2: R15.2 U3.1 | length 9
  Top Layer w0.2: U3.1 33.466,21.655 v1(33.655,21.844) ; v1(34.544,27.94) R15.2
  Bottom Layer w0.2: v1(33.655,21.844) 34.544,22.733 34.544,27.686 34.29,27.94 v1(34.544,27.94)
NetR16_2: R16.2 U3.30 | length 11.6
  Top Layer w0.2: U3.30 35.548,19.927 35.75,20.13 v1@35.75,20.383 ; v1(36.195,27.94) R16.2
  Bottom Layer w0.2: v1(35.814,20.32) 35.814,27.559 v1(36.195,27.94)
NetR17_2: R17.2 U3.27 | length 19.8
  Top Layer w0.2: U3.27 39.231,18.427 40.005,17.653 v1(40.386,17.653) ; v1(41.275,26.67) 41.275,27.305 42.672,28.702 R17.2
  Bottom Layer w0.2: v1(40.386,17.653) 40.386,26.035 41.021,26.67 v1(41.275,26.67)
NetR18_2: R18.2 Switch.7 | length 11.4
  Top Layer w0.254: R18.2 v1(21.844,30.48) ; v1@29.718,31.496 30.511,30.703 Switch.7
  Bottom Layer w0.254: v1(21.844,30.48) 27.686,30.48 28.829,31.623 v1(29.591,31.623)
NetR20_2: R20.2 U3.23 | length 22.2
  Top Layer w0.2: U3.23 32.238,16.149 32.893,15.494 39.243,15.494 v1(39.497,15.748) ; v1(39.751,26.67) 39.751,27.305 41.148,28.702 R20.2
  Bottom Layer w0.2: v1(39.497,15.748) 39.497,26.416 v1(39.751,26.67)
NetR21_2: R21.2 U3.24 | length 18.9
  Top Layer w0.2: U3.24 33.181,16.256 v1@38.1,16.256 ; v1(38.481,26.67) 38.481,27.305 39.497,28.321 R21.2
  Bottom Layer w0.2: v1(38.1,16.383) 38.1,26.289 v1(38.481,26.67)
NetR22_2: R22.2 U3.25 | length 15.9
  Top Layer w0.2: U3.25 33.627,17.427 33.909,17.145 v1(36.83,17.145) ; v1(37.211,26.67) 37.211,27.432 37.846,28.067 R22.2
  Bottom Layer w0.2: v1(36.83,17.145) 36.83,26.289 v1(37.211,26.67)
NetR23_2: R23.2 Switch.3 | length 2.4
  Top Layer w0.254: Switch.3 26.511,28.326 R23.2@27.305,27.532
NetR25_2: R25.2 Switch.6 | length 2.3
  Top Layer w0.254: R25.2 29.511,28.214 Switch.6
SPEED: C5.1 R24.2 R25.1 U3.6 | length 10.9
  Top Layer w0.2: R25.1@28.892,25.971 27.432,24.511 27.432,23.622 27.94,23.114 29.591,23.114 30.238,22.467 U3.6
  Top Layer w0.254: R25.1@28.829,25.781 R25.1 C5.1 R24.2@32.385,26.035
START: R19.2 U3.21 | length 33.5
  Top Layer w0.2: U3.21 31.238,15.498 v1(31.496,15.24)
  Top Layer w0.254: R19.2 11.276,32.512 v1(11.684,32.512)
  Bottom Layer w0.254: v1(11.684,32.512) 10.795,31.623 10.795,28.956 18.034,21.717 19.812,21.717 21.717,19.812 26.924,19.812 v1(31.496,15.24)
STARTX: Q7.3 R26.2 Switch.4 | length 26.3
  Top Layer w0.254: R26.2 8.863,26.688 Q7.3 9.198,27.613 10.033,28.448 10.033,29.718 v1@11.62,31.305 ; v1(27.218,31.457) 27.511,31.163 Switch.4
  Bottom Layer w0.254: v1(11.684,31.242) 11.938,31.496 27.257,31.496 v1(27.218,31.457)
SWCLK: J1.3 U3.5 | length 19.6
  Top Layer w0.2: v1(28.321,24.003) 29.464,24.003 30.738,22.729 U3.5
  Bottom Layer w0.2: v1(28.321,24.003) 28.321,20.828 34.798,14.351 35.687,14.351 36.957,13.081 J1.3
SWDIO/KEY: J1.2 R32.2 U3.17 | length 15.8
  Top Layer w0.2: R32.2 27.659,12.8 v1(27.305,12.446) 26.924,12.827 26.924,14.732 28.891,16.699 U3.17
  Bottom Layer w0.2: v1(27.305,12.446) 28.035,11.716 34.163,11.716 J1.2
VDD: C2.2 C15.2 C22.1 J1.1 R2.2 R13.1 R18.1 R29.1 R30.1 U3.13 U5.2 | length 70.9
  Top Layer w0.2: C15.2 22.284,15.807 R30.1 ; v1@23.05,16.573 23.241,16.764 ; v1(23.622,16.891) 23.876,16.891 24.765,16.891 26.801,18.927 U3.13
  Top Layer w0.254: R18.1 21.844,26.289 R29.1 R13.1 v1(23.749,25.146)
  Top Layer w0.4: U5.2 6.223,17.78 5.148,16.705 C2.2 6.037,13.843 16.625,13.843 C22.1 20.367,16.014 C15.2 ; R30.1 22.352,16.383 22.796,16.828 23.114,17.145 23.749,17.145 23.876,17.018 23.876,16.764 23.622,16.764 23.241,16.764 ; R2.2 32.866,13.081 J1.1
  Bottom Layer w0.4: v1(23.749,25.146) 25.273,25.146 26.162,24.257 26.162,21.844 33.528,14.478 J1.1 31.115,13.081 30.226,13.97 29.464,13.97 26.289,17.145 23.241,17.145 v1(22.86,16.764) 23.749,16.764 24.003,17.018
VMA: C10.1 R8.2 R9.1 U3.19 | length 29.7
  Top Layer w0.2: v1(29.845,15.113) 30.238,15.506 U3.19
  Top Layer w0.254: R8.2 10.668,27.078 R9.1 C10.1
  Bottom Layer w0.254: v1(10.668,26.924) 11.43,26.924 17.526,20.828 19.685,20.828 21.336,19.177 26.289,19.177 29.845,15.621 v1(29.845,15.113)
VMB: C8.1 R6.2 R7.1 U3.8 | length 20.5
  Top Layer w0.2: v1(21.082,22.479) 21.59,21.971 26.543,21.971 26.859,21.655 U3.8
  Top Layer w0.254: R7.1@13.97,26.162 v1(15.113,26.162) ; R6.2@13.97,27.586 13.97,25.908 15.621,25.908
  Bottom Layer w0.254: v1(15.113,26.162) 18.796,22.479 v1(21.082,22.479)
VMC: C7.1 R4.2 R5.1 U3.4 | length 21.2
  Top Layer w0.2: v1(29.591,24.765) 31.238,23.118 U3.4
  Top Layer w0.254: R4.2@17.272,27.586 R4.2@17.335,27.523 ; R5.1 C7.1 19.304,25.527 20.828,24.003 v1(21.971,24.003) ; 17.399,25.908 R4.2@17.399,27.459 ; R4.2@17.399,27.586 R4.2@17.68,27.305
  Bottom Layer w0.2: v1(21.971,24.003) 21.971,25.527 22.345,25.901 29.217,25.901 29.591,25.527 v1(29.591,24.765)
VOLDECT: C19.1 R35.2 R36.1 U3.9 | length 21.2
  Top Layer w0.2: R35.2 13.943,21.363 C19.1 14.097,21.463 25.654,21.463 26.19,20.927 U3.9
pads on no net: U5.3 U5.4 U5.5 U5.7

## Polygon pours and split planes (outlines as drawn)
GND on Top Layer "Top Layer-No Net" (solid, remove dead copper, pour order 15): 0.264,33.543 32.385,33.528 33.782,32.131 33.782,27.94 36.83,24.892 36.83,22.225 37.338,21.717 49.53,21.717 49.53,20.701 49.547,10.685 39.639,0.777 4.074,0.777 4.074,0.904 0.264,4.714
DCIN on Top Layer "Bottom Layer-No Net" (solid, remove dead copper, pour order 11): 25.654,56.388 26.035,56.007 26.035,54.483 25.781,54.229 19.431,54.229 16.637,51.435 9.144,51.435 7.366,49.657 7.366,42.418 9.144,40.64 12.065,40.64 12.192,40.513 12.192,36.195 17.653,36.195 17.653,39.878 18.288,40.513 25.527,40.513 25.781,40.259 25.781,37.211 31.496,37.211 31.496,40.513 31.623,40.64 38.608,40.64 38.862,40.386 38.862,34.163 38.608,33.909 31.75,33.909 31.496,34.163 31.496,37.211 25.781,37.211 25.781,34.036 25.654,33.909 17.907,33.909 17.653,34.163 17.653,36.195 12.192,36.195 12.192,34.036 12.065,33.909 3.429,33.909 2.413,34.925 2.413,47.879 8.001,53.467 13.208,53.467 17.018,57.277 19.177,57.277 20.066,56.388
MOTOR_B on Top Layer "TopGnd" (solid, remove dead copper, pour order 32): 22.352,50.8 21.971,50.419 21.971,41.529 22.352,41.148 26.035,41.148 26.67,40.513 26.67,37.592 27.051,37.211 30.226,37.211 30.734,37.719 30.734,42.799 29.464,44.069 29.464,50.546 29.21,50.8
MOTOR_C on Top Layer "TopGnd" (solid, remove dead copper, pour order 30): 41.783,50.8 34.671,50.8 34.29,50.419 34.29,44.069 33.782,43.561 32.766,43.561 32.258,43.053 32.258,41.529 32.639,41.148 39.243,41.148 39.751,40.64 39.751,37.465 40.132,37.084 44.069,37.084 44.704,37.719 44.704,41.529 42.037,44.196 42.037,50.546
MOTOR_A on Top Layer "TopGnd" (solid, remove dead copper, pour order 34): 16.637,50.8 9.652,50.8 9.398,50.546 9.398,44.069 12.319,41.148 13.081,41.148 13.208,41.021 13.208,37.338 13.462,37.084 16.637,37.084 16.891,37.338 16.891,40.513 17.526,41.148 20.574,41.148 20.955,41.529 20.955,43.18 20.32,43.815 17.272,43.815 16.764,44.323 16.764,50.673
ISENCE on Top Layer "TopGnd" (solid, remove dead copper, pour order 20): 18.034,48.895 18.034,52.197 19.558,53.721 43.942,53.721 46.228,51.435 46.228,48.133 45.847,47.752 43.815,47.752 43.18,48.387 43.18,50.546 42.545,51.181 34.163,51.181 33.655,50.673 33.655,48.387 33.274,48.006 31.115,48.006 30.607,48.514 30.607,50.673 30.099,51.181 21.971,51.181 21.463,50.673 21.463,48.895 20.955,48.387 18.542,48.387
GND on Top Layer "TopGnd" (solid, remove dead copper, pour order 36): 27.051,54.229 36.322,54.229 37.338,55.245 37.338,58.674 36.195,59.817 16.383,59.817 12.192,55.626 6.858,55.626 0.254,49.022 0.254,14.224 1.651,12.827 1.905,13.081 1.905,48.387 7.62,54.102 12.954,54.102 16.637,57.785 19.558,57.785 20.447,56.896 26.289,56.896 26.67,56.515 26.67,54.61
GND on Bottom Layer "Top Layer-No Net" (solid, remove dead copper, pour order 21): 0.127,33.02 23.622,33.02 25.019,31.623 31.242,31.623 33.909,28.956 33.909,22.733 45.434,11.208 45.434,2.508 43.307,0.381 4.318,0.381 3.937,0 0.127,3.81
MOTOR_C on Bottom Layer "TopGnd" (solid, remove dead copper, pour order 28): 32.512,41.148 32.004,41.656 32.004,44.958 33.401,46.355 33.401,50.419 33.909,50.927 43.561,50.927 45.212,49.276 45.212,38.227 44.196,37.211 40.386,37.211 39.751,37.846 39.751,40.64 39.243,41.148
MOTOR_B on Bottom Layer "TopGnd" (solid, remove dead copper, pour order 26): 21.844,50.927 21.463,50.546 21.463,41.656 21.971,41.148 26.035,41.148 26.67,40.513 26.67,38.354 27.178,37.846 30.099,37.846 30.861,38.608 30.861,41.021 31.496,41.656 31.496,50.546 31.115,50.927
MOTOR_A on Bottom Layer "TopGnd" (solid, remove dead copper, pour order 24): 10.16,51.943 8.128,49.911 8.128,42.926 9.906,41.148 12.827,41.148 13.081,40.894 13.081,38.1 13.335,37.846 17.018,37.846 17.272,38.1 17.272,40.259 18.161,41.148 20.447,41.148 20.955,41.656 20.955,45.466 19.558,46.863 19.558,50.419 18.034,51.943
GND on Bottom Layer "Bottom Layer-No Net" (solid, remove dead copper, pour order 16): 36.322,54.229 37.338,55.245 37.338,58.801 36.322,59.817 21.59,59.817 21.082,59.309 21.082,58.166 21.59,57.658 25.781,57.658 26.797,56.642 26.797,53.975 27.051,53.721 32.385,53.721 32.893,54.229
DCIN on Bottom Layer "TopGnd" (solid, remove dead copper, pour order 22): 25.4,57.15 21.463,57.15 18.923,59.69 16.256,59.69 12.192,55.626 6.985,55.626 2.413,51.054 2.413,33.909 2.794,33.528 38.735,33.528 39.243,34.036 39.243,40.132 38.735,40.64 31.877,40.64 31.369,40.132 31.369,38.354 30.226,37.211 27.051,37.211 26.162,38.1 26.162,40.132 25.654,40.64 18.669,40.64 17.907,39.878 17.907,37.973 17.018,37.084 13.081,37.084 12.573,37.592 12.573,40.259 12.192,40.64 9.144,40.64 7.366,42.418 7.366,50.546 9.525,52.705 24.511,52.705 26.289,54.483 26.289,56.261

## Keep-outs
Keep-Out Layer:
  circle w0.127: c24.832,12.423 r0.65
  circle w0.127: c4.004,7.724 r0.65
  circle w0.127: c47.865,5.119 r1
  circle w0.127: c11.203,57.858 r1
  lines w0.1: 0,4.318 0,49.228 10.954,60.182 38.719,60.182 49.673,49.228 49.673,4.318 45.434,0.079 4.239,0.079 0,4.318

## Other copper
Top Layer:
  pour cut-out: 32.766,21.463 33.147,21.082 33.147,17.108 32.738,16.699 28.894,16.699 28.51,17.083 28.51,21.017 28.956,21.463

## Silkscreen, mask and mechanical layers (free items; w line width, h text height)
Top Overlay:
  lines w0.127: 9.53,58.683 ccw(c11.303,57.758) 10.378,59.531 ; 49.673,4.619 cw(c47.765,5.219) 49.673,5.819
  lines w0.3: 3.357,2.438 3.357,12.979 25.424,12.979 25.424,2.438 3.357,2.438
  text "黑" at 33.782,57.277 h1.02
  text "红" at 15.621,56.769 h1.02
  text "白" at 30.861,43.434 h1.02
  text "黄" at 44.196,42.799 h1.02
  text "蓝" at 8.89,42.037 h1.02
Bottom Overlay:
  drawing of 1973 lines, arcs and shapes, not listed
  text "LCP018BK32EU8-DB-V1.0-2022.2.12" at 39.086,14.359 h1
Top Solder:
  lines w1: 19.939,52.324 29.718,52.324 ; 38.608,52.324 43.688,52.324
Bottom Solder:
  rectangle: 34.29,45.466 42.926,50.673
  rectangle: 22.098,45.466 30.353,50.673
  rectangle: 9.398,45.466 17.653,50.673
  region: 38.735,39.104 31.623,39.104 31.623,33.897 38.735,33.897
  region: 25.654,39.104 18.542,39.104 18.542,33.897 25.654,33.897
  region: 12.192,39.104 5.08,39.104 5.08,33.897 12.192,33.897
  lines w1: 13.963,42.037 13.074,42.545 13.963,43.053 ; 14.739,42.037 15.628,42.545 14.739,43.053 ; 19.163,42.037 18.274,42.545 19.163,43.053 ; 23.361,42.037 22.472,42.545 23.361,43.053 ; 24.137,42.037 25.026,42.545 24.137,43.053 ; 28.561,42.037 27.672,42.545 28.561,43.053 ; 29.337,42.037 30.226,42.545 29.337,43.053 ; 33.916,42.037 34.805,42.545 33.916,43.053 ; 38.34,42.037 37.451,42.545 38.34,43.053 ; 38.728,42.545 40.005,42.545 ; 39.116,42.037 40.005,42.545 ; 39.116,43.053 40.005,42.545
